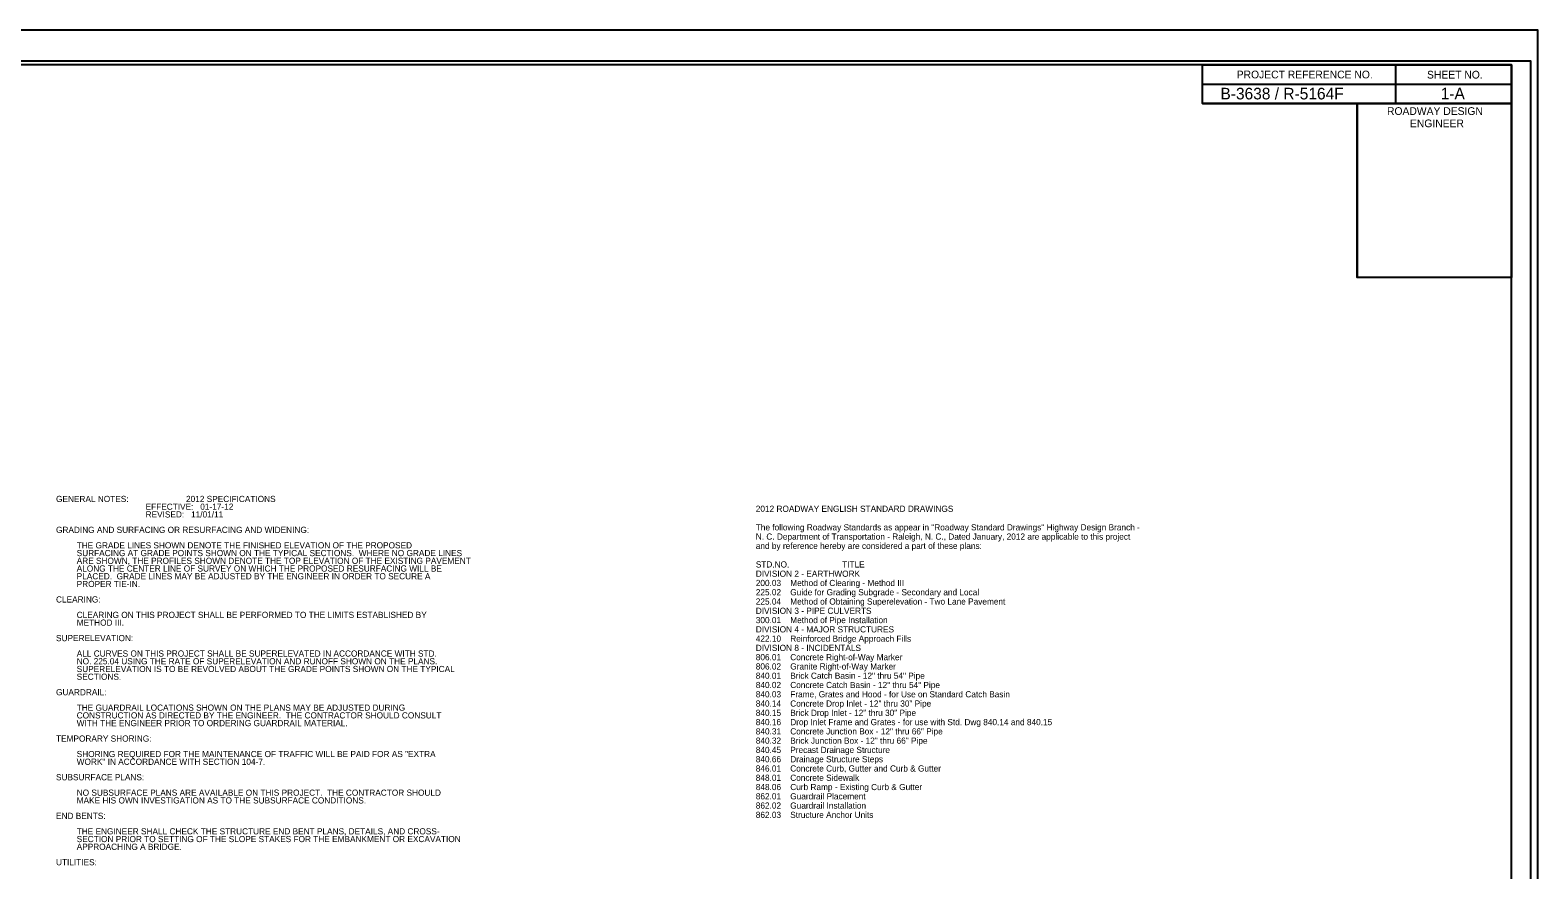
# Model space of a CAD drawing. Extents: x 573851.6 to 573885.3, y -53299.4 to -53277.5.
# Drawn here: x 573865.75 to 573885.26, y -53288.41 to -53277.55 of the extents above; entities that cross this region are included whole.
import ezdxf

# ---------------------------------------------------------------- set-up
doc = ezdxf.new("R2010")
doc.units = 0
for name, color, linetype in [('Default', 7, 'Continuous'), ('Old_Level_2', 7, 'Continuous'), ('Old_Level_4', 7, 'Continuous'), ('Sheet Cutting Line CELL', 7, 'Continuous'), ('Sheet Data Field CELL', 7, 'Continuous'), ('Sheet Plot Border Inside CELL', 7, 'Continuous')]:
    doc.layers.add(name, color=color, linetype=linetype)

msp = doc.modelspace()

# ---------------------------------------------------------------- linework, layer by layer
at = {"layer": 'Old_Level_2'}
for p, q in [((573883.42, -53278), (573883.42, -53278.5)), ((573880.919, -53278.25), (573884.92, -53278.25)), ((573880.919, -53278.5), (573884.92, -53278.5)), ((573880.919, -53278.5), (573884.92, -53278.5)), ((573882.92, -53278.5), (573882.92, -53280.749))]:
    msp.add_line(p, q, dxfattribs=at)
for points in [[(573884.92, -53277.999), (573854.92, -53277.999), (573854.92, -53298.999), (573884.92, -53298.999)], [(573880.919, -53277.999), (573884.92, -53277.999), (573884.92, -53278.5), (573880.919, -53278.5)], [(573882.92, -53278.5), (573884.92, -53278.5), (573884.92, -53280.75), (573882.92, -53280.75)]]:
    msp.add_lwpolyline(points, close=True, dxfattribs=at)
at = {"layer": 'Old_Level_4'}
msp.add_lwpolyline([(573851.59, -53299.449), (573885.26, -53299.449), (573885.26, -53277.549), (573851.59, -53277.549)], close=True, dxfattribs=at)
at = {"layer": 'Sheet Cutting Line CELL'}
msp.add_line((573885.26, -53277.549), (573851.59, -53277.549), dxfattribs=at)
at = {"layer": 'Sheet Plot Border Inside CELL'}
msp.add_lwpolyline([(573851.85, -53299.049), (573885.17, -53299.049), (573885.17, -53277.949), (573851.85, -53277.949)], close=True, dxfattribs=at)

# ---------------------------------------------------------------- texts
at = {"layer": 'Default'}
for s, p in [('GENERAL NOTES:                         2012 SPECIFICATIONS', (573866.085, -53283.654)), ('                                       EFFECTIVE:   01-17-12', (573866.085, -53283.754)), ('                                       REVISED:   11/01/11', (573866.085, -53283.854)), ('2012 ROADWAY ENGLISH STANDARD DRAWINGS', (573875.14, -53283.781)), ('GRADING AND SURFACING OR RESURFACING AND WIDENING:  ', (573866.085, -53284.054)), ('The following Roadway Standards as appear in "Roadway Standard Drawings" Highway Design Branch -', (573875.14, -53284.021)), ('N. C. Department of Transportation - Raleigh, N. C., Dated January, 2012 are applicable to this project', (573875.14, -53284.141)), ('         THE GRADE LINES SHOWN DENOTE THE FINISHED ELEVATION OF THE PROPOSED ', (573866.085, -53284.254)), ('and by reference hereby are considered a part of these plans:', (573875.14, -53284.261)), ('         ARE SHOWN, THE PROFILES SHOWN DENOTE THE TOP ELEVATION OF THE EXISTING PAVEMENT ', (573866.085, -53284.454)), ('         SURFACING AT GRADE POINTS SHOWN ON THE TYPICAL SECTIONS.  WHERE NO GRADE LINES ', (573866.085, -53284.354)), ('STD.NO.                       TITLE', (573875.14, -53284.501)), ('         ALONG THE CENTER LINE OF SURVEY ON WHICH THE PROPOSED RESURFACING WILL BE ', (573866.085, -53284.554)), ('         PLACED.  GRADE LINES MAY BE ADJUSTED BY THE ENGINEER IN ORDER TO SECURE A ', (573866.085, -53284.654)), ('DIVISION 2 - EARTHWORK', (573875.14, -53284.621)), ('         PROPER TIE-IN.  ', (573866.085, -53284.754)), ('200.03    Method of Clearing - Method III', (573875.14, -53284.741)), ('225.02    Guide for Grading Subgrade - Secondary and Local', (573875.14, -53284.861)), ('CLEARING:  ', (573866.085, -53284.954)), ('225.04    Method of Obtaining Superelevation - Two Lane Pavement', (573875.14, -53284.981)), ('DIVISION 3 - PIPE CULVERTS', (573875.14, -53285.101)), ('         CLEARING ON THIS PROJECT SHALL BE PERFORMED TO THE LIMITS ESTABLISHED BY ', (573866.085, -53285.154)), ('         METHOD III.', (573866.085, -53285.254)), ('300.01    Method of Pipe Installation ', (573875.14, -53285.221)), ('SUPERELEVATION:  ', (573866.085, -53285.454)), ('422.10    Reinforced Bridge Approach Fills', (573875.14, -53285.461)), ('DIVISION 4 - MAJOR STRUCTURES', (573875.14, -53285.341)), ('         ALL CURVES ON THIS PROJECT SHALL BE SUPERELEVATED IN ACCORDANCE WITH STD. ', (573866.085, -53285.654)), ('806.01    Concrete Right-of-Way Marker', (573875.14, -53285.701)), ('DIVISION 8 - INCIDENTALS', (573875.14, -53285.581)), ('         SUPERELEVATION IS TO BE REVOLVED ABOUT THE GRADE POINTS SHOWN ON THE TYPICAL ', (573866.085, -53285.854)), ('         NO. 225.04 USING THE RATE OF SUPERELEVATION AND RUNOFF SHOWN ON THE PLANS.', (573866.085, -53285.754)), ('806.02    Granite Right-of-Way Marker', (573875.14, -53285.821)), ('         SECTIONS.  ', (573866.085, -53285.954)), ('840.01    Brick Catch Basin - 12" thru 54" Pipe', (573875.14, -53285.941)), ('840.02    Concrete Catch Basin - 12" thru 54" Pipe', (573875.14, -53286.061)), ('GUARDRAIL:  ', (573866.085, -53286.154)), ('840.03    Frame, Grates and Hood - for Use on Standard Catch Basin', (573875.14, -53286.181)), ('         THE GUARDRAIL LOCATIONS SHOWN ON THE PLANS MAY BE ADJUSTED DURING ', (573866.085, -53286.354)), ('         CONSTRUCTION AS DIRECTED BY THE ENGINEER.  THE CONTRACTOR SHOULD CONSULT', (573866.085, -53286.454)), ('840.14    Concrete Drop Inlet - 12" thru 30" Pipe', (573875.14, -53286.301)), ('840.15    Brick Drop Inlet - 12" thru 30" Pipe', (573875.14, -53286.421)), ('         WITH THE ENGINEER PRIOR TO ORDERING GUARDRAIL MATERIAL.', (573866.085, -53286.554)), ('840.16    Drop Inlet Frame and Grates - for use with Std. Dwg 840.14 and 840.15', (573875.14, -53286.541)), ('840.31    Concrete Junction Box - 12" thru 66" Pipe', (573875.14, -53286.661)), ('TEMPORARY SHORING:  ', (573866.085, -53286.754)), ('840.32    Brick Junction Box - 12" thru 66" Pipe', (573875.14, -53286.781)), ('         WORK" IN ACCORDANCE WITH SECTION 104-7.  ', (573866.085, -53287.054)), ('         SHORING REQUIRED FOR THE MAINTENANCE OF TRAFFIC WILL BE PAID FOR AS "EXTRA ', (573866.085, -53286.954)), ('840.45    Precast Drainage Structure', (573875.14, -53286.901)), ('840.66    Drainage Structure Steps', (573875.14, -53287.021)), ('SUBSURFACE PLANS:  ', (573866.085, -53287.254)), ('846.01    Concrete Curb, Gutter and Curb & Gutter', (573875.14, -53287.141)), ('848.01    Concrete Sidewalk', (573875.14, -53287.261)), ('         NO SUBSURFACE PLANS ARE AVAILABLE ON THIS PROJECT.  THE CONTRACTOR SHOULD ', (573866.085, -53287.454)), ('848.06    Curb Ramp - Existing Curb & Gutter', (573875.14, -53287.381)), ('         MAKE HIS OWN INVESTIGATION AS TO THE SUBSURFACE CONDITIONS.  ', (573866.085, -53287.554)), ('862.01    Guardrail Placement', (573875.14, -53287.501)), ('862.02    Guardrail Installation', (573875.14, -53287.621)), ('END BENTS:  ', (573866.085, -53287.754)), ('862.03    Structure Anchor Units', (573875.14, -53287.741)), ('         THE ENGINEER SHALL CHECK THE STRUCTURE END BENT PLANS, DETAILS, AND CROSS-', (573866.085, -53287.954)), ('         APPROACHING A BRIDGE.  ', (573866.085, -53288.154)), ('         SECTION PRIOR TO SETTING OF THE SLOPE STAKES FOR THE EMBANKMENT OR EXCAVATION ', (573866.085, -53288.054)), ('UTILITIES:  ', (573866.085, -53288.354))]:
    msp.add_text(s, height=0.08, dxfattribs=at).set_placement(p)
at = {"layer": 'Old_Level_2'}
for s, p in [('PROJECT REFERENCE NO.', (573881.363, -53278.173)), ('SHEET NO.', (573883.826, -53278.175)), ('ROADWAY DESIGN', (573883.308, -53278.646)), ('ENGINEER', (573883.605, -53278.805))]:
    msp.add_text(s, height=0.1, dxfattribs=at).set_placement(p)
at = {"layer": 'Sheet Data Field CELL'}
for s, p in [('B-3638 / R-5164F', (573881.153, -53278.445)), ('1-A', (573884.003, -53278.444))]:
    msp.add_text(s, height=0.15, dxfattribs=at).set_placement(p)

doc.saveas('drawing.dxf')
